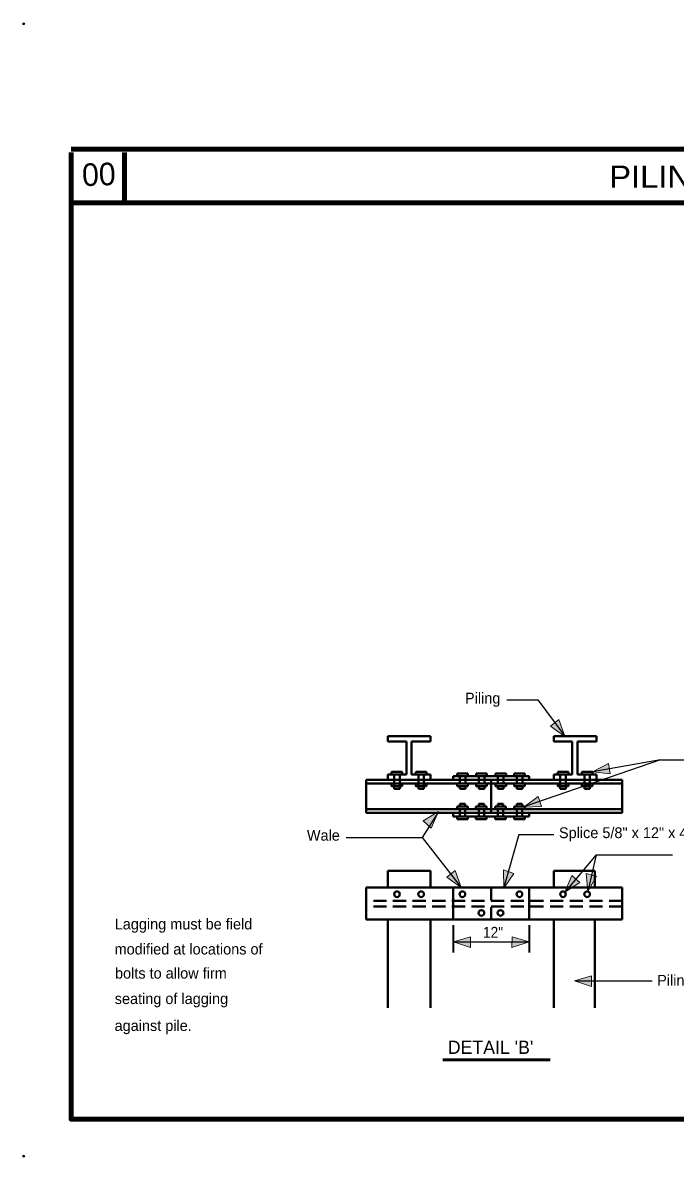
# Model space of a CAD drawing. Extents: x -8731 to -2098, y -70205 to -56618.
# Drawn here: x -3692 to -3004, y -70205 to -69010 of the extents above; entities that cross this region are included whole.
import ezdxf
from ezdxf.enums import TextEntityAlignment as Align

# ---------------------------------------------------------------- set-up
doc = ezdxf.new("R2010")
doc.units = 0
doc.header["$LTSCALE"] = 4.6
doc.header["$PDMODE"] = 32
doc.header["$PDSIZE"] = 2.3
doc.linetypes.add('MEDIUM_DASHED', pattern=[4.5, 3, -1.5])
doc.layers.add('1', color=7, linetype='Continuous', lineweight=13)
doc.layers.add('3', color=7, linetype='Continuous', lineweight=40)

msp = doc.modelspace()

# ---------------------------------------------------------------- hatches: boundary and pattern name
at = {"layer": '1'}
for points in [[(-3120.62, -69762.04), (-3127.06, -69744.12), (-3135.82, -69751.16)], [(-3091.52, -69799.32), (-3074.62, -69790.52), (-3072.98, -69801.64)], [(-3163.98, -69836.72), (-3148.82, -69825.24), (-3145.32, -69835.92)], [(-3253.98, -69841.32), (-3261.72, -69858.72), (-3269.94, -69851.04)], [(-3229.96, -69921.26), (-3236.4, -69903.34), (-3245.16, -69910.4)], [(-3184.96, -69921.8), (-3185.2, -69902.76), (-3174.52, -69906.3)], [(-3120.64, -69926.08), (-3113.18, -69908.56), (-3104.82, -69916.1)], [(-3096.5, -69925.4), (-3098.1, -69906.44), (-3087.2, -69909.2)], [(-3238.1, -69978.42), (-3220.02, -69984.38), (-3220.16, -69973.12)], [(-3158.42, -69978.42), (-3176.5, -69984.38), (-3176.34, -69973.12)], [(-3110.58, -70019.66), (-3092.5, -70025.64), (-3092.66, -70014.38)]]:
    msp.add_hatch(color=256, dxfattribs=at).paths.add_polyline_path(points)

# ---------------------------------------------------------------- linework, layer by layer
at = {"layer": '1', "lineweight": 100}
for p, q in [((-2148.78, -69143.8), (-3641.02, -69143.8)), ((-3584.76, -69147.3), (-3584.76, -69200.06)), ((-2148.78, -69200.06), (-3641.02, -69200.06))]:
    msp.add_line(p, q, dxfattribs=at)
msp.add_lwpolyline([(-3641.02, -69147.3), (-3641.02, -70165.24), (-2150.26, -70165.24)], dxfattribs=at)
at = {"layer": '1'}
for points in [[(-3120.62, -69762.04), (-3127.06, -69744.12), (-3135.82, -69751.16)], [(-3091.52, -69799.32), (-3074.62, -69790.52), (-3072.98, -69801.64)], [(-3163.98, -69836.72), (-3148.82, -69825.24), (-3145.32, -69835.92)], [(-3253.98, -69841.32), (-3261.72, -69858.72), (-3269.94, -69851.04)], [(-3229.96, -69921.26), (-3236.4, -69903.34), (-3245.16, -69910.4)], [(-3184.96, -69921.8), (-3185.2, -69902.76), (-3174.52, -69906.3)], [(-3120.64, -69926.08), (-3113.18, -69908.56), (-3104.82, -69916.1)], [(-3096.5, -69925.4), (-3098.1, -69906.44), (-3087.2, -69909.2)], [(-3238.1, -69978.42), (-3220.02, -69984.38), (-3220.16, -69973.12)], [(-3158.42, -69978.42), (-3176.5, -69984.38), (-3176.34, -69973.12)], [(-3110.58, -70019.66), (-3092.5, -70025.64), (-3092.66, -70014.38)]]:
    msp.add_lwpolyline(points, close=True, dxfattribs=at)
for p in [(-3690.94, -69011.6), (-3690.94, -70204.2)]:
    msp.add_point(p, dxfattribs=at)
at = {"layer": '3', "lineweight": 25}
for p, q in [((-3181.96, -69723.72), (-3149.26, -69723.72)), ((-3149.26, -69723.72), (-3120.76, -69761.66)), ((-3019.82, -69786.86), (-3162.92, -69835.92)), ((-3019.82, -69786.86), (-3091.52, -69799.32)), ((-3019.82, -69786.86), (-2716.52, -69786.86)), ((-3169.06, -69865.46), (-3184.96, -69921.26)), ((-3169.06, -69865.46), (-3132.46, -69865.46)), ((-3351.16, -69868.62), (-3270.92, -69868.62)), ((-3087.62, -69886.92), (-3120.62, -69926.06)), ((-3087.62, -69886.92), (-3096.46, -69925.32)), ((-3087.62, -69886.92), (-3007.36, -69886.92)), ((-3238.52, -69978.42), (-3158.42, -69978.42)), ((-3109.06, -70019.36), (-3028.82, -70019.36))]:
    msp.add_line(p, q, dxfattribs=at)
at = {"layer": '3'}
for p, q in [((-3307.36, -69761.66), (-3262.36, -69761.66)), ((-3307.36, -69761.66), (-3307.36, -69767.36)), ((-3307.36, -69767.36), (-3287.72, -69767.36)), ((-3287.72, -69767.36), (-3287.72, -69802.16)), ((-3282.16, -69767.36), (-3282.16, -69802.16)), ((-3282.16, -69767.36), (-3262.36, -69767.36)), ((-3262.36, -69761.66), (-3262.36, -69767.36)), ((-3132.46, -69761.66), (-3087.46, -69761.66)), ((-3132.46, -69761.66), (-3132.46, -69767.36)), ((-3132.46, -69767.36), (-3112.82, -69767.36)), ((-3112.82, -69767.36), (-3112.82, -69802.16)), ((-3107.26, -69767.36), (-3107.26, -69802.16)), ((-3107.26, -69767.36), (-3087.46, -69767.36)), ((-3087.46, -69761.66), (-3087.46, -69767.36)), ((-3307.36, -69802.16), (-3307.36, -69807.86)), ((-3307.36, -69802.16), (-3287.72, -69802.16)), ((-3303.32, -69799.32), (-3292.06, -69799.32)), ((-3303.32, -69799.32), (-3303.32, -69802.16)), ((-3292.06, -69799.32), (-3292.06, -69802.16)), ((-3282.16, -69802.16), (-3262.36, -69802.16)), ((-3277.82, -69799.32), (-3266.56, -69799.32)), ((-3277.82, -69799.32), (-3277.82, -69802.16)), ((-3266.56, -69799.32), (-3266.56, -69802.16)), ((-3262.36, -69802.16), (-3262.36, -69807.86)), ((-3238.52, -69803.96), (-3238.52, -69807.86)), ((-3234.16, -69801.12), (-3222.92, -69801.12)), ((-3234.16, -69801.12), (-3234.16, -69803.96)), ((-3222.92, -69801.12), (-3222.92, -69803.96)), ((-3214.22, -69801.12), (-3202.96, -69801.12)), ((-3214.22, -69801.12), (-3214.22, -69803.96)), ((-3202.96, -69801.12), (-3202.96, -69803.96)), ((-3193.96, -69801.12), (-3182.72, -69801.12)), ((-3193.96, -69801.12), (-3193.96, -69803.96)), ((-3182.72, -69801.12), (-3182.72, -69803.96)), ((-3174.02, -69801.12), (-3162.76, -69801.12)), ((-3174.02, -69801.12), (-3174.02, -69803.96)), ((-3162.76, -69801.12), (-3162.76, -69803.96)), ((-3158.42, -69803.96), (-3158.42, -69807.86)), ((-3132.46, -69802.16), (-3132.46, -69807.86)), ((-3132.46, -69802.16), (-3112.82, -69802.16)), ((-3128.12, -69799.32), (-3117.02, -69799.32)), ((-3128.12, -69799.32), (-3128.12, -69802.16)), ((-3117.02, -69799.32), (-3117.02, -69802.16)), ((-3107.26, -69802.16), (-3087.46, -69802.16)), ((-3102.76, -69799.32), (-3091.52, -69799.32)), ((-3102.76, -69799.32), (-3102.76, -69802.16)), ((-3091.52, -69799.32), (-3091.52, -69802.16)), ((-3087.46, -69802.16), (-3087.46, -69807.86)), ((-3330.16, -69807.86), (-3060.32, -69807.86)), ((-3330.16, -69807.86), (-3330.16, -69842.66)), ((-3330.16, -69811.62), (-3060.32, -69811.62)), ((-3300.46, -69814.46), (-3300.46, -69817.46)), ((-3300.46, -69817.46), (-3294.62, -69817.46)), ((-3294.62, -69814.46), (-3294.62, -69817.46)), ((-3292.06, -69811.62), (-3292.06, -69814.46)), ((-3274.96, -69814.46), (-3274.96, -69817.46)), ((-3274.96, -69817.46), (-3269.26, -69817.46)), ((-3269.26, -69814.46), (-3269.26, -69817.46)), ((-3266.56, -69811.62), (-3266.56, -69814.46)), ((-3231.32, -69814.46), (-3231.32, -69817.46)), ((-3231.32, -69817.46), (-3225.46, -69817.46)), ((-3225.46, -69814.46), (-3225.46, -69817.46)), ((-3222.92, -69811.62), (-3222.92, -69814.46)), ((-3211.36, -69814.46), (-3211.36, -69817.46)), ((-3211.36, -69817.46), (-3205.52, -69817.46)), ((-3205.52, -69814.46), (-3205.52, -69817.46)), ((-3202.96, -69811.62), (-3202.96, -69814.46)), ((-3198.46, -69842.66), (-3198.46, -69807.86)), ((-3191.26, -69814.46), (-3191.26, -69817.46)), ((-3191.26, -69817.46), (-3185.42, -69817.46)), ((-3185.42, -69814.46), (-3185.42, -69817.46)), ((-3182.72, -69811.62), (-3182.72, -69814.46)), ((-3171.16, -69814.46), (-3171.16, -69817.46)), ((-3171.16, -69817.46), (-3165.46, -69817.46)), ((-3165.46, -69814.46), (-3165.46, -69817.46)), ((-3162.76, -69811.62), (-3162.76, -69814.46)), ((-3125.56, -69814.46), (-3125.56, -69817.46)), ((-3125.56, -69817.46), (-3119.72, -69817.46)), ((-3119.72, -69814.46), (-3119.72, -69817.46)), ((-3117.02, -69811.62), (-3117.02, -69814.46)), ((-3100.06, -69814.46), (-3100.06, -69817.46)), ((-3100.06, -69817.46), (-3094.36, -69817.46)), ((-3094.36, -69814.46), (-3094.36, -69817.46)), ((-3091.52, -69811.62), (-3091.52, -69814.46)), ((-3060.32, -69807.86), (-3060.32, -69842.66)), ((-3330.16, -69838.76), (-3060.32, -69838.76)), ((-3234.32, -69838.92), (-3234.32, -69835.92)), ((-3231.46, -69835.92), (-3231.46, -69832.92)), ((-3225.76, -69832.92), (-3231.46, -69832.92)), ((-3225.76, -69835.92), (-3225.76, -69832.92)), ((-3214.36, -69838.92), (-3214.36, -69835.92)), ((-3211.52, -69835.92), (-3211.52, -69832.92)), ((-3205.66, -69832.92), (-3211.52, -69832.92)), ((-3205.66, -69835.92), (-3205.66, -69832.92)), ((-3194.12, -69838.92), (-3194.12, -69835.92)), ((-3191.42, -69835.92), (-3191.42, -69832.92)), ((-3185.56, -69832.92), (-3191.42, -69832.92)), ((-3185.56, -69835.92), (-3185.56, -69832.92)), ((-3174.16, -69838.92), (-3174.16, -69835.92)), ((-3171.46, -69835.92), (-3171.46, -69832.92)), ((-3165.62, -69832.92), (-3171.46, -69832.92)), ((-3165.62, -69835.92), (-3165.62, -69832.92)), ((-3330.16, -69842.66), (-3060.32, -69842.66)), ((-3238.52, -69846.56), (-3238.52, -69842.66)), ((-3234.32, -69849.26), (-3234.32, -69846.56)), ((-3223.06, -69849.26), (-3234.32, -69849.26)), ((-3223.06, -69849.26), (-3223.06, -69846.56)), ((-3214.36, -69849.26), (-3214.36, -69846.56)), ((-3203.12, -69849.26), (-3214.36, -69849.26)), ((-3203.12, -69849.26), (-3203.12, -69846.56)), ((-3194.12, -69849.26), (-3194.12, -69846.56)), ((-3183.02, -69849.26), (-3194.12, -69849.26)), ((-3183.02, -69849.26), (-3183.02, -69846.56)), ((-3174.16, -69849.26), (-3174.16, -69846.56)), ((-3162.92, -69849.26), (-3174.16, -69849.26)), ((-3162.92, -69849.26), (-3162.92, -69846.56)), ((-3158.42, -69846.56), (-3158.42, -69842.66)), ((-3307.36, -69903.56), (-3262.36, -69903.56)), ((-3307.36, -69903.56), (-3307.36, -69921.26)), ((-3262.36, -69903.56), (-3262.36, -69921.26)), ((-3132.46, -69903.56), (-3088.96, -69903.56)), ((-3132.46, -69903.56), (-3132.46, -69921.26)), ((-3088.96, -69903.56), (-3088.96, -69921.26)), ((-3330.16, -69921.26), (-3060.32, -69921.26)), ((-3330.16, -69921.26), (-3330.16, -69955.02)), ((-3238.52, -69921.26), (-3238.52, -69955.02)), ((-3158.42, -69921.26), (-3158.42, -69955.02)), ((-3060.32, -69921.26), (-3060.32, -69955.02)), ((-3330.16, -69955.02), (-3060.32, -69955.02)), ((-3307.36, -69955.02), (-3307.36, -70047.86)), ((-3262.36, -69955.02), (-3262.36, -70047.86)), ((-3132.46, -69955.02), (-3132.46, -70047.86)), ((-3088.96, -69955.02), (-3088.96, -70047.86))]:
    msp.add_line(p, q, dxfattribs=at)
at = {"layer": '3', "linetype": 'MEDIUM_DASHED'}
for p, q in [((-3300.46, -69802.16), (-3300.46, -69814.46)), ((-3294.62, -69802.16), (-3294.62, -69814.46)), ((-3274.96, -69802.16), (-3274.96, -69814.46)), ((-3269.26, -69802.16), (-3269.26, -69814.46)), ((-3231.32, -69803.96), (-3231.32, -69811.62)), ((-3225.46, -69803.96), (-3225.46, -69811.62)), ((-3211.36, -69803.96), (-3211.36, -69811.62)), ((-3205.52, -69803.96), (-3205.52, -69811.62)), ((-3191.26, -69803.96), (-3191.26, -69811.62)), ((-3185.42, -69803.96), (-3185.42, -69811.62)), ((-3171.16, -69803.96), (-3171.16, -69811.62)), ((-3165.46, -69803.96), (-3165.46, -69811.62)), ((-3125.56, -69802.16), (-3125.56, -69814.46)), ((-3119.72, -69802.16), (-3119.72, -69814.46)), ((-3100.06, -69802.16), (-3100.06, -69814.46)), ((-3094.36, -69802.16), (-3094.36, -69814.46)), ((-3231.46, -69846.56), (-3231.46, -69838.92)), ((-3225.76, -69846.56), (-3225.76, -69838.92)), ((-3211.52, -69846.56), (-3211.52, -69838.92)), ((-3205.66, -69846.56), (-3205.66, -69838.92)), ((-3191.42, -69846.56), (-3191.42, -69838.92)), ((-3185.56, -69846.56), (-3185.56, -69838.92)), ((-3171.46, -69846.56), (-3171.46, -69838.92)), ((-3165.62, -69846.56), (-3165.62, -69838.92)), ((-3198.46, -69921.26), (-3198.46, -69955.02)), ((-3060.32, -69935.22), (-3330.16, -69935.22)), ((-3060.32, -69941.06), (-3330.16, -69941.06))]:
    msp.add_line(p, q, dxfattribs=at)
at = {"layer": '3', "lineweight": 35}
for p, q in [((-3238.52, -69960.72), (-3238.52, -69989.52)), ((-3158.42, -69960.72), (-3158.42, -69989.52))]:
    msp.add_line(p, q, dxfattribs=at)
at = {"layer": '3', "lineweight": 53}
msp.add_line((-3249.16, -70102.62), (-3136.06, -70102.62), dxfattribs=at)
at = {"layer": '3'}
for points in [[(-3238.52, -69803.96), (-3218.42, -69803.96), (-3198.46, -69803.96)], [(-3198.46, -69803.96), (-3178.36, -69803.96), (-3158.42, -69803.96)], [(-3303.32, -69811.62), (-3303.32, -69814.46), (-3292.06, -69814.46)], [(-3277.82, -69811.62), (-3277.82, -69814.46), (-3266.56, -69814.46)], [(-3234.16, -69811.62), (-3234.16, -69814.46), (-3222.92, -69814.46)], [(-3214.22, -69811.62), (-3214.22, -69814.46), (-3202.96, -69814.46)], [(-3193.96, -69811.62), (-3193.96, -69814.46), (-3182.72, -69814.46)], [(-3174.02, -69811.62), (-3174.02, -69814.46), (-3162.76, -69814.46)], [(-3128.12, -69811.62), (-3128.12, -69814.46), (-3117.02, -69814.46)], [(-3102.76, -69811.62), (-3102.76, -69814.46), (-3091.52, -69814.46)], [(-3223.06, -69838.92), (-3223.06, -69835.92), (-3234.32, -69835.92)], [(-3203.12, -69838.92), (-3203.12, -69835.92), (-3214.36, -69835.92)], [(-3183.02, -69838.92), (-3183.02, -69835.92), (-3194.12, -69835.92)], [(-3162.92, -69838.92), (-3162.92, -69835.92), (-3174.16, -69835.92)], [(-3198.46, -69846.56), (-3218.56, -69846.56), (-3238.52, -69846.56)], [(-3158.42, -69846.56), (-3178.52, -69846.56), (-3198.46, -69846.56)]]:
    msp.add_lwpolyline(points, dxfattribs=at)
at = {"layer": '3', "lineweight": 25}
msp.add_lwpolyline([(-3254.56, -69842.66), (-3270.92, -69868.62), (-3229.96, -69921.26)], dxfattribs=at)
at = {"layer": '3'}
for centre in [(-3297.6, -69928.25), (-3272.19, -69928.25), (-3228.63, -69928.25), (-3168.55, -69928.25), (-3122.63, -69928.25), (-3097.22, -69928.25), (-3208.66, -69948.04), (-3188.51, -69948.04)]:
    msp.add_circle(centre, 3, dxfattribs=at)

# ---------------------------------------------------------------- texts
at = {"layer": '1'}
msp.add_text('00', height=23.78, rotation=2.121, dxfattribs=at).set_placement((-3629.06, -69182.68))
at = {"layer": '3', "width": 1.1}
msp.add_text('  PILING DETAILS (3 OF 3) ', height=23.4, dxfattribs=at).set_placement((-2876.86, -69184.32), align=Align.CENTER)
at = {"layer": '3'}
for s, height, p in [('Piling', 11.4, (-3225.92, -69727.46)), ('Wale', 11.4, (-3392.56, -69871.92)), ('Splice 5/8" x 12" x 4" Plate', 11.4, (-3126.92, -69869.22)), ('Lagging must be field', 11.4, (-3595.06, -69965.36)), ('modified at locations of', 11.4, (-3595.22, -69991.76)), ('bolts to allow firm', 11.4, (-3594.76, -70017.12)), ('Piling', 11.4, (-3023.42, -70024.62)), ('seating of lagging', 11.4, (-3595.06, -70043.96)), ('against pile.', 11.4, (-3595.22, -70072.32)), ("DETAIL 'B'", 13.95, (-3244.06, -70096.46))]:
    msp.add_text(s, height=height, dxfattribs=at).set_placement(p)
at = {"layer": '3', "width": 0.95}
msp.add_text('12"', height=11.4, dxfattribs=at).set_placement((-3207.02, -69974.06))

doc.saveas('drawing.dxf')
